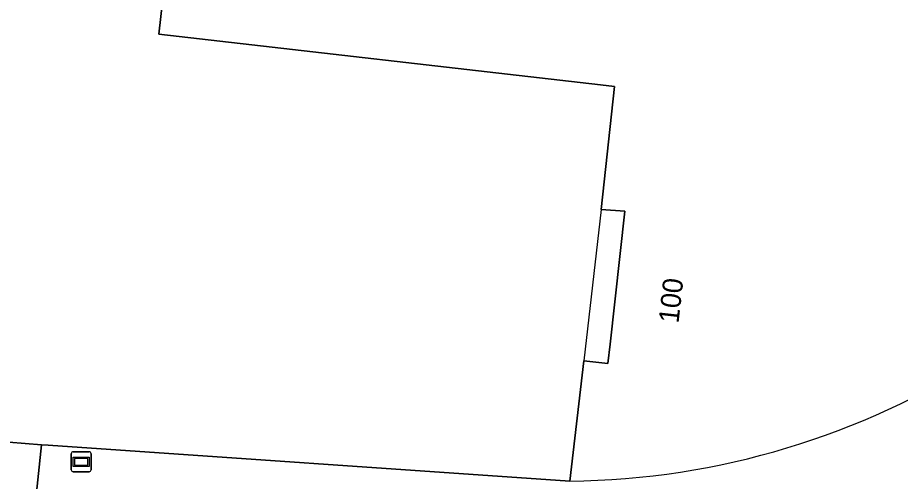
# Model space of a CAD drawing. Extents: x 161385 to 162589, y 388479 to 389756.
# Drawn here: x 162418.94 to 162462.97, y 388672.98 to 388696.11 of the extents above; entities that cross this region are included whole.
import ezdxf

# ---------------------------------------------------------------- set-up
doc = ezdxf.new("R2010")
doc.units = 0
for name, color, linetype in [('IMGEO_Erf', 7, 'Continuous'), ('IMGEO_Groenvoorziening', 7, 'Continuous'), ('IMGEO_Hek', 7, 'Continuous'), ('IMGEO_Informatiebord', 7, 'Continuous'), ('IMGEO_Muur', 7, 'Continuous'), ('IMGEO_Pand', 7, 'Continuous'), ('IMGEO_Pand_nummerreeks', 7, 'Continuous'), ('IMGEO_Pand_overbouw', 7, 'Continuous'), ('IMGEO_Voetpad_open', 7, 'Continuous')]:
    doc.layers.add(name, color=color, linetype=linetype)

msp = doc.modelspace()

# ---------------------------------------------------------------- linework, layer by layer
at = {"layer": 'IMGEO_Erf'}
msp.add_lwpolyline([(162383.967, 388722.64), (162411.707, 388719.457), (162406.76, 388675.873), (162412.776, 388675.396), (162420.122, 388674.813), (162420.461, 388674.786), (162446.489, 388672.997), (162447.18, 388679), (162448.384, 388678.861), (162448.49, 388679.822), (162449.227, 388686.456), (162448.051, 388686.549), (162448.713, 388692.673), (162448.008, 388692.753), (162425.971, 388695.283), (162429.384, 388725.33), (162435.4, 388724.653), (162435.751, 388727.776), (162406.633, 388731.063), (162412.095, 388778.923)], dxfattribs=at)
at = {"layer": 'IMGEO_Groenvoorziening'}
for points in [[(162420.122, 388674.813), (162419.797, 388671.622)], [(162420.461, 388674.786), (162420.122, 388674.813)], [(162446.489, 388672.997), (162420.461, 388674.786)]]:
    msp.add_lwpolyline(points, dxfattribs=at)
msp.add_arc((162446.053, 388712.081), 39.087, 270.6397, 334.4773, dxfattribs=at)
at = {"layer": 'IMGEO_Hek'}
for points in [[(162420.122, 388674.813), (162412.776, 388675.396)], [(162420.461, 388674.786), (162420.122, 388674.813)]]:
    msp.add_lwpolyline(points, dxfattribs=at)
at = {"layer": 'IMGEO_Informatiebord'}
for p, q in [((162421.611, 388673.563), (162421.611, 388674.363)), ((162421.611, 388674.363), (162421.611, 388673.563)), ((162421.711, 388674.463), (162422.501, 388674.463)), ((162422.501, 388674.463), (162421.711, 388674.463)), ((162422.601, 388674.363), (162422.601, 388673.563)), ((162422.601, 388673.563), (162422.601, 388674.363)), ((162422.501, 388673.463), (162421.711, 388673.463)), ((162421.711, 388673.463), (162422.501, 388673.463))]:
    msp.add_line(p, q, dxfattribs=at)
for points in [[(162421.712, 388674.195), (162422.5, 388674.195), (162422.5, 388673.731), (162421.712, 388673.731), (162421.712, 388674.195)], [(162421.777, 388674.13), (162421.777, 388673.796), (162422.435, 388673.796), (162422.435, 388674.13), (162421.777, 388674.13)]]:
    msp.add_lwpolyline(points, dxfattribs=at)
for centre, start, end in [((162421.711, 388674.363), 90, 180), ((162421.711, 388674.363), 90, 180), ((162422.501, 388674.363), 0, 90), ((162422.501, 388674.363), 360, 90), ((162421.711, 388673.563), 180, 270), ((162421.711, 388673.563), 180, 270), ((162422.501, 388673.563), 270, 0), ((162422.501, 388673.563), 270, 0)]:
    msp.add_arc(centre, 0.1, start, end, dxfattribs=at)
at = {"layer": 'IMGEO_Muur'}
msp.add_lwpolyline([(162446.489, 388672.997), (162420.461, 388674.786)], dxfattribs=at)
at = {"layer": 'IMGEO_Pand'}
msp.add_lwpolyline([(162491.877, 388718.298), (162438.622, 388724.29), (162438.974, 388727.412), (162435.751, 388727.776), (162435.4, 388724.653), (162429.384, 388725.33), (162425.971, 388695.283), (162448.008, 388692.753), (162448.713, 388692.673), (162448.051, 388686.549), (162449.227, 388686.456), (162448.49, 388679.822), (162448.384, 388678.861), (162447.18, 388679), (162446.489, 388672.997)], dxfattribs=at)
msp.add_arc((162446.053, 388712.081), 39.087, 270.6397, 334.4773, dxfattribs=at)
at = {"layer": 'IMGEO_Pand_overbouw'}
msp.add_lwpolyline([(162448.051, 388686.549), (162447.18, 388679), (162448.384, 388678.861), (162448.49, 388679.822), (162449.227, 388686.456)], close=True, dxfattribs=at)
at = {"layer": 'IMGEO_Voetpad_open'}
msp.add_lwpolyline([(162419.785, 388671.507), (162419.797, 388671.622), (162420.122, 388674.813), (162412.776, 388675.396), (162412.421, 388672.249), (162412.286, 388671.047), (162412.183, 388670.136), (162419.72, 388669.598), (162419.748, 388670.416)], close=True, dxfattribs=at)

# ---------------------------------------------------------------- texts
at = {"layer": 'IMGEO_Pand_nummerreeks'}
msp.add_text('100', height=1, rotation=83.6633, dxfattribs=at).set_placement((162451.904, 388680.841))

doc.saveas('drawing.dxf')
